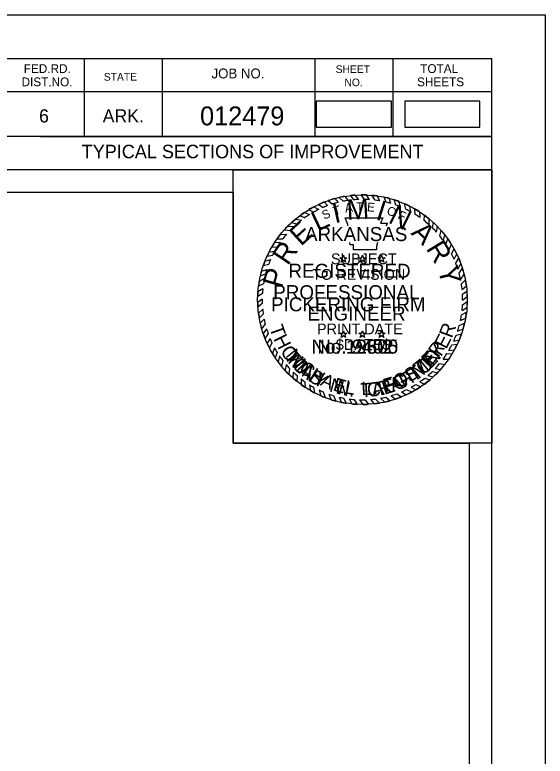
# Model space of a CAD drawing. Extents: x 1373889 to 1374222, y 382002 to 382215.
# Drawn here: x 1374174.7 to 1374221.8, y 382149.1 to 382215 of the extents above; entities that cross this region are included whole.
import ezdxf

# ---------------------------------------------------------------- set-up
doc = ezdxf.new("R2010")
doc.units = 0
for name, color, linetype in [('Default', 7, 'Continuous'), ('R_Border', 7, 'Continuous'), ('R_Border Notes', 7, 'Continuous'), ('R_No Plot', 7, 'Continuous'), ('STAMP_PE_CRAFTON', 7, 'Continuous'), ('STAMP_PE_FOSTER', 7, 'Continuous'), ('STAMP_PE_SEAL-INFO', 7, 'Continuous'), ('STAMP_PE_TAEGTMEYER', 7, 'Continuous'), ('STAMP_PE_TXT', 7, 'Continuous'), ('STAMP_PRELIMINARY', 7, 'Continuous')]:
    doc.layers.add(name, color=color, linetype=linetype)

msp = doc.modelspace()

# ---------------------------------------------------------------- linework, layer by layer
at = {"layer": 'Default'}
for points in [[(1374201.483, 382205.02), (1374208.166, 382205.02), (1374208.166, 382207.33), (1374201.483, 382207.33)], [(1374209.353, 382205.02), (1374216.036, 382205.02), (1374216.036, 382207.33), (1374209.353, 382207.33)]]:
    msp.add_lwpolyline(points, close=True, dxfattribs=at)
at = {"layer": 'R_Border'}
for p, q in [((1373900.915, 382211.115), (1374217.095, 382211.115)), ((1374180.835, 382211.115), (1374180.835, 382204.175)), ((1374187.775, 382211.115), (1374187.775, 382204.175)), ((1374201.355, 382211.115), (1374201.355, 382204.175)), ((1374208.295, 382211.115), (1374208.295, 382204.175)), ((1374217.095, 382005.655), (1374217.095, 382211.115)), ((1374217.095, 382208.175), (1374173.995, 382208.175)), ((1374217.095, 382208.195), (1374217.095, 382208.195)), ((1374217.095, 382204.175), (1374173.995, 382204.175)), ((1374176.955, 382204.175), (1374217.095, 382204.175)), ((1374217.095, 382201.235), (1374154.455, 382201.235))]:
    msp.add_line(p, q, dxfattribs=at)
at = {"layer": 'R_No Plot'}
for points in [[(1373888.507, 382215.01), (1374221.847, 382215.01), (1374221.847, 382001.672), (1373888.507, 382001.672)], [(1374215.095, 382110.385), (1373902.915, 382110.385), (1373902.915, 382209.115), (1374152.455, 382209.115), (1374152.455, 382199.235), (1374169.995, 382199.235), (1374194.095, 382199.235), (1374194.095, 382176.903), (1374215.095, 382176.903)], [(1373902.915, 382209.115), (1374152.455, 382209.115), (1374152.455, 382199.235), (1374169.995, 382199.235), (1374194.095, 382199.235), (1374194.095, 382176.903), (1374215.095, 382176.903), (1374215.095, 382007.655), (1373902.915, 382007.655)], [(1374194.095, 382201.235), (1374217.095, 382201.235), (1374217.095, 382176.903), (1374194.095, 382176.903)]]:
    msp.add_lwpolyline(points, close=True, dxfattribs=at)
at = {"layer": 'STAMP_PE_SEAL-INFO'}
for p, q in [((1374203.533, 382198.769), (1374203.889, 382198.426)), ((1374204.016, 382198.866), (1374204.315, 382198.499)), ((1374204.531, 382198.939), (1374204.812, 382198.557)), ((1374205.267, 382198.585), (1374204.955, 382198.978)), ((1374205.765, 382198.59), (1374205.486, 382199)), ((1374206.223, 382198.569), (1374205.964, 382198.993)), ((1374206.728, 382198.519), (1374206.436, 382198.962)), ((1374207.154, 382198.454), (1374206.897, 382198.909)), ((1374207.716, 382198.335), (1374207.542, 382198.795)), ((1374208.118, 382198.227), (1374207.959, 382198.696)), ((1374201.699, 382198.147), (1374202.088, 382197.872)), ((1374202.207, 382198.363), (1374202.501, 382198.037)), ((1374202.554, 382198.491), (1374202.935, 382198.185)), ((1374203.145, 382198.673), (1374203.433, 382198.325)), ((1374208.57, 382198.08), (1374208.428, 382198.559)), ((1374208.988, 382197.92), (1374208.844, 382198.416)), ((1374209.449, 382197.715), (1374209.347, 382198.212)), ((1374200.433, 382197.441), (1374200.875, 382197.239)), ((1374200.82, 382197.685), (1374201.252, 382197.462)), ((1374201.268, 382197.935), (1374201.731, 382197.71)), ((1374209.895, 382197.485), (1374209.808, 382197.994)), ((1374210.283, 382197.259), (1374210.243, 382197.759)), ((1374210.717, 382196.972), (1374210.686, 382197.487)), ((1374199.636, 382196.847), (1374200.165, 382196.746)), ((1374200.013, 382197.174), (1374200.468, 382196.969)), ((1374204.068, 382196.969), (1374207.412, 382196.969)), ((1374204.189, 382196.662), (1374204.068, 382196.969)), ((1374207.412, 382196.969), (1374207.187, 382196.477)), ((1374211.078, 382196.705), (1374211.112, 382197.193)), ((1374211.524, 382196.333), (1374211.544, 382196.856)), ((1374198.957, 382196.223), (1374199.501, 382196.182)), ((1374199.292, 382196.547), (1374199.751, 382196.408)), ((1374204.293, 382196.364), (1374204.189, 382196.662)), ((1374204.3, 382196.249), (1374204.293, 382196.364)), ((1374207.187, 382196.477), (1374207.82, 382196.477)), ((1374207.82, 382196.477), (1374207.675, 382196.249)), ((1374211.837, 382196.041), (1374211.906, 382196.539)), ((1374212.196, 382195.667), (1374212.263, 382196.193)), ((1374198.288, 382195.468), (1374198.837, 382195.49)), ((1374198.634, 382195.879), (1374199.155, 382195.841)), ((1374212.47, 382195.351), (1374212.606, 382195.822)), ((1374212.794, 382194.934), (1374212.929, 382195.433)), ((1374197.776, 382194.754), (1374198.292, 382194.788)), ((1374198.01, 382195.098), (1374198.515, 382195.093)), ((1374204.492, 382194.541), (1374204.465, 382194.758)), ((1374206.929, 382194.758), (1374206.851, 382194.448)), ((1374213.014, 382194.619), (1374213.191, 382195.082)), ((1374197.529, 382194.353), (1374198.019, 382194.373)), ((1374204.806, 382194.541), (1374204.492, 382194.541)), ((1374204.806, 382194.11), (1374204.806, 382194.541)), ((1374206.836, 382194.11), (1374204.806, 382194.11)), ((1374206.851, 382194.448), (1374206.836, 382194.11)), ((1374213.322, 382194.121), (1374213.504, 382194.613)), ((1374213.521, 382193.755), (1374213.748, 382194.199)), ((1374197.11, 382193.541), (1374197.613, 382193.645)), ((1374197.298, 382193.93), (1374197.797, 382193.995)), ((1374213.752, 382193.271), (1374213.978, 382193.756)), ((1374196.776, 382192.702), (1374197.261, 382192.838)), ((1374196.926, 382193.108), (1374197.431, 382193.255)), ((1374213.893, 382192.934), (1374214.156, 382193.367)), ((1374214.087, 382192.385), (1374214.358, 382192.859)), ((1374196.62, 382192.199), (1374197.097, 382192.368)), ((1374214.195, 382192.02), (1374214.489, 382192.472)), ((1374196.879, 382191.545), (1374196.414, 382191.296)), ((1374196.515, 382191.792), (1374196.985, 382191.984)), ((1374214.328, 382191.461), (1374214.647, 382191.908)), ((1374196.794, 382191.087), (1374196.348, 382190.864)), ((1374214.397, 382191.081), (1374214.751, 382191.434)), ((1374214.463, 382190.572), (1374214.836, 382190.908)), ((1374196.698, 382190.226), (1374196.277, 382189.969)), ((1374196.735, 382190.651), (1374196.298, 382190.37)), ((1374214.496, 382190.154), (1374214.886, 382190.446)), ((1374196.682, 382189.733), (1374196.276, 382189.397)), ((1374214.497, 382189.231), (1374214.916, 382189.508)), ((1374214.508, 382189.636), (1374214.913, 382189.958)), ((1374196.688, 382189.326), (1374196.297, 382189.001)), ((1374196.722, 382188.83), (1374196.35, 382188.474)), ((1374214.457, 382188.725), (1374214.892, 382188.981)), ((1374196.773, 382188.401), (1374196.419, 382188.028)), ((1374214.407, 382188.336), (1374214.85, 382188.556)), ((1374196.852, 382187.942), (1374196.513, 382187.575)), ((1374196.946, 382187.523), (1374196.633, 382187.108)), ((1374214.208, 382187.385), (1374214.68, 382187.586)), ((1374214.316, 382187.836), (1374214.771, 382188.032)), ((1374197.069, 382187.076), (1374196.775, 382186.658)), ((1374214.061, 382186.89), (1374214.552, 382187.091)), ((1374197.21, 382186.653), (1374196.929, 382186.241)), ((1374197.376, 382186.227), (1374197.115, 382185.804)), ((1374213.927, 382186.51), (1374214.409, 382186.641)), ((1374197.548, 382185.843), (1374197.321, 382185.383)), ((1374213.552, 382185.66), (1374214.04, 382185.728)), ((1374213.713, 382185.996), (1374214.201, 382186.092)), ((1374197.783, 382185.385), (1374197.592, 382184.895)), ((1374198.019, 382184.981), (1374197.835, 382184.511)), ((1374213.108, 382184.881), (1374213.585, 382184.874)), ((1374213.279, 382185.161), (1374213.78, 382185.215)), ((1374198.221, 382184.67), (1374198.112, 382184.118)), ((1374198.502, 382184.279), (1374198.4, 382183.749)), ((1374212.768, 382184.386), (1374213.273, 382184.389)), ((1374198.806, 382183.902), (1374198.719, 382183.382)), ((1374199.109, 382183.564), (1374199.047, 382183.042)), ((1374212.077, 382183.559), (1374212.554, 382183.474)), ((1374212.46, 382183.992), (1374212.922, 382183.913)), ((1374199.431, 382183.239), (1374199.401, 382182.71)), ((1374199.775, 382182.926), (1374199.772, 382182.397)), ((1374211.416, 382182.928), (1374211.887, 382182.799)), ((1374211.822, 382183.3), (1374212.263, 382183.162)), ((1374200.135, 382182.632), (1374200.154, 382182.107)), ((1374200.474, 382182.382), (1374200.51, 382181.864)), ((1374210.685, 382182.36), (1374211.124, 382182.171)), ((1374211.145, 382182.703), (1374211.613, 382182.558)), ((1374200.901, 382182.1), (1374200.962, 382181.588)), ((1374201.251, 382181.894), (1374201.342, 382181.381)), ((1374201.732, 382181.644), (1374201.889, 382181.123)), ((1374209.519, 382181.674), (1374210.003, 382181.463)), ((1374209.927, 382181.887), (1374210.344, 382181.655)), ((1374210.341, 382182.133), (1374210.791, 382181.937)), ((1374202.105, 382181.476), (1374202.278, 382180.965)), ((1374202.597, 382181.283), (1374202.807, 382180.782)), ((1374203.007, 382181.148), (1374203.233, 382180.659)), ((1374203.515, 382181.01), (1374203.727, 382180.544)), ((1374203.912, 382180.924), (1374204.159, 382180.466)), ((1374207.196, 382180.909), (1374207.584, 382180.57)), ((1374207.688, 382181.013), (1374208.066, 382180.688)), ((1374208.148, 382181.137), (1374208.564, 382180.84)), ((1374208.64, 382181.301), (1374209.083, 382181.032)), ((1374209.06, 382181.465), (1374209.483, 382181.204)), ((1374204.413, 382180.843), (1374204.652, 382180.403)), ((1374204.849, 382180.795), (1374205.123, 382180.367)), ((1374205.334, 382180.768), (1374205.636, 382180.355)), ((1374205.794, 382180.766), (1374206.137, 382180.371)), ((1374206.312, 382180.793), (1374206.638, 382180.413)), ((1374206.75, 382180.839), (1374207.123, 382180.481))]:
    msp.add_line(p, q, dxfattribs=at)
for radius, start, end in [(9.323, 99.75254, 102.77648), (9.323, 93.93815, 96.55172), (9.323, 87.72979, 90.67067), (9.323, 81.97315, 84.82355), (9.323, 75.31251, 77.94263), (9.323, 111.31242, 114.70259), (8.914, 110.30864, 113.16588), (9.323, 105.23389, 109.03519), (8.914, 104.03521, 107.36155), (8.914, 98.25799, 101.03289), (8.914, 92.11016, 95.03666), (8.914, 85.96279, 88.9097), (8.914, 79.92642, 82.69597), (8.914, 73.55748, 76.23144), (9.323, 69.60611, 72.30577), (8.914, 67.62483, 70.50398), (9.323, 63.13288, 66.2704), (9.323, 123.61993, 126.59063), (9.323, 117.65441, 120.80988), (8.914, 115.68692, 119.15827), (8.914, 61.15575, 64.37837), (9.323, 56.90029, 60.09423), (9.323, 129.73259, 132.53764), (8.914, 127.52969, 130.96829), (8.914, 121.97456, 125.11001), (8.914, 54.92383, 58.27016), (9.323, 50.3492, 53.71593), (9.323, 135.40208, 138.30314), (8.914, 133.13306, 136.25623), (8.914, 48.30163, 52.03953), (9.323, 44.3405, 47.39292), (9.323, 141.60556, 144.44865), (8.914, 139.30101, 142.58729), (8.914, 42.22116, 45.55119), (9.323, 38.12472, 41.23157), (9.323, 147.00719, 149.89904), (8.914, 145.01972, 148.21036), (8.914, 36.13503, 39.53106), (9.323, 31.96138, 35.42937), (8.914, 29.90321, 33.66454), (9.323, 25.93909, 29.01247), (9.323, 152.86398, 155.51889), (8.914, 151.03153, 153.57304), (8.914, 23.77322, 27.22114), (9.323, 158.40766, 161.07015), (8.914, 156.34018, 159.23194), (8.914, 17.68022, 21.42509), (9.323, 19.95381, 23.31409), (9.323, 164.3068, 166.89395), (8.914, 162.43309, 165.00133), (9.323, 13.84205, 17.44468), (8.914, 167.90481, 170.90393), (8.914, 11.54445, 15.23639), (9.323, 170.0003, 172.68778), (8.914, 5.7599, 9.06056), (9.323, 7.58519, 10.86211), (9.323, 175.74093, 178.2066), (8.914, 173.73, 176.47337), (8.914, 359.73289, 3.06392), (9.323, 1.72155, 4.72681), (8.914, 179.64537, 182.26333), (9.323, 355.71562, 358.95694), (9.323, 181.72508, 184.16255), (8.914, 185.45389, 188.23401), (8.914, 353.86319, 357.12742), (9.323, 187.42037, 190.19271), (8.914, 348.07782, 351.34355), (9.323, 349.83047, 353.08845), (9.323, 193.03695, 195.99732), (8.914, 191.22736, 193.98583), (9.323, 343.89247, 347.03502), (8.914, 196.96751, 199.83526), (8.914, 341.77699, 345.09248), (9.323, 198.89671, 201.62812), (8.914, 202.77613, 205.47915), (8.914, 335.6038, 339.18578), (9.323, 337.38367, 340.99332), (9.323, 204.54793, 207.43282), (8.914, 329.55488, 333.20757), (9.323, 331.40371, 334.93315), (9.323, 210.86355, 213.65709), (8.914, 208.78826, 211.79343), (8.914, 323.58513, 327.44069), (9.323, 325.44052, 328.98725), (8.914, 214.18375, 217.27474), (9.323, 216.61154, 219.49098), (8.914, 220.39088, 223.30564), (8.914, 316.65308, 320.37109), (9.323, 318.28455, 321.80429), (9.323, 222.47995, 225.38008), (8.914, 226.24938, 229.24068), (8.914, 310.77436, 314.31605), (9.323, 312.45177, 315.66328), (9.323, 228.36648, 231.34802), (8.914, 232.22904, 234.93361), (8.914, 304.82299, 308.51428), (9.323, 306.37206, 310.20799), (9.323, 234.29502, 236.94517), (8.914, 238.22227, 240.83529), (9.323, 240.1977, 242.86128), (8.914, 244.32043, 246.94859), (8.914, 292.87452, 296.11851), (8.914, 299.07679, 302.17235), (9.323, 300.62101, 303.87026), (9.323, 246.57598, 249.15579), (8.914, 250.34912, 253.12157), (8.914, 256.50505, 259.11916), (8.914, 280.34588, 283.58137), (8.914, 286.64233, 289.97826), (9.323, 288.57086, 291.97334), (9.323, 294.64808, 298.21662), (9.323, 252.59667, 255.32518), (9.323, 258.44328, 261.13983), (8.914, 262.37828, 265.20115), (9.323, 264.19784, 267.10092), (8.914, 268.3215, 271.27698), (9.323, 270.25484, 273.33609), (8.914, 274.61565, 277.44863), (9.323, 276.42389, 279.43574), (9.323, 282.31994, 285.37019)]:
    msp.add_arc((1374205.595, 382189.678), radius, start, end, dxfattribs=at)
at = {"layer": 'STAMP_PE_TXT'}
for p, q in [((1374203.821, 382193.393), (1374203.897, 382193.626)), ((1374203.897, 382193.626), (1374203.973, 382193.393)), ((1374205.519, 382193.393), (1374205.595, 382193.626)), ((1374205.595, 382193.626), (1374205.671, 382193.393)), ((1374207.217, 382193.393), (1374207.293, 382193.626)), ((1374207.293, 382193.626), (1374207.369, 382193.393)), ((1374203.774, 382193.249), (1374203.576, 382193.393)), ((1374203.576, 382193.393), (1374203.821, 382193.393)), ((1374203.699, 382193.016), (1374203.774, 382193.249)), ((1374203.897, 382193.16), (1374203.699, 382193.016)), ((1374204.095, 382193.016), (1374203.897, 382193.16)), ((1374203.973, 382193.393), (1374204.218, 382193.393)), ((1374204.218, 382193.393), (1374204.02, 382193.249)), ((1374204.02, 382193.249), (1374204.095, 382193.016)), ((1374205.472, 382193.249), (1374205.274, 382193.393)), ((1374205.274, 382193.393), (1374205.519, 382193.393)), ((1374205.397, 382193.016), (1374205.472, 382193.249)), ((1374205.595, 382193.16), (1374205.397, 382193.016)), ((1374205.793, 382193.016), (1374205.595, 382193.16)), ((1374205.671, 382193.393), (1374205.916, 382193.393)), ((1374205.916, 382193.393), (1374205.718, 382193.249)), ((1374205.718, 382193.249), (1374205.793, 382193.016)), ((1374207.17, 382193.249), (1374206.972, 382193.393)), ((1374206.972, 382193.393), (1374207.217, 382193.393)), ((1374207.095, 382193.016), (1374207.17, 382193.249)), ((1374207.293, 382193.16), (1374207.095, 382193.016)), ((1374207.491, 382193.016), (1374207.293, 382193.16)), ((1374207.369, 382193.393), (1374207.614, 382193.393)), ((1374207.614, 382193.393), (1374207.416, 382193.249)), ((1374207.416, 382193.249), (1374207.491, 382193.016)), ((1374203.821, 382186.686), (1374203.897, 382186.919)), ((1374203.897, 382186.919), (1374203.973, 382186.686)), ((1374205.519, 382186.686), (1374205.595, 382186.919)), ((1374205.595, 382186.919), (1374205.671, 382186.686)), ((1374207.217, 382186.686), (1374207.293, 382186.919)), ((1374207.293, 382186.919), (1374207.369, 382186.686)), ((1374203.774, 382186.542), (1374203.576, 382186.686)), ((1374203.576, 382186.686), (1374203.821, 382186.686)), ((1374203.699, 382186.309), (1374203.774, 382186.542)), ((1374203.897, 382186.453), (1374203.699, 382186.309)), ((1374204.095, 382186.309), (1374203.897, 382186.453)), ((1374203.973, 382186.686), (1374204.218, 382186.686)), ((1374204.218, 382186.686), (1374204.02, 382186.542)), ((1374204.02, 382186.542), (1374204.095, 382186.309)), ((1374205.472, 382186.542), (1374205.274, 382186.686)), ((1374205.274, 382186.686), (1374205.519, 382186.686)), ((1374205.397, 382186.309), (1374205.472, 382186.542)), ((1374205.595, 382186.453), (1374205.397, 382186.309)), ((1374205.793, 382186.309), (1374205.595, 382186.453)), ((1374205.671, 382186.686), (1374205.916, 382186.686)), ((1374205.916, 382186.686), (1374205.718, 382186.542)), ((1374205.718, 382186.542), (1374205.793, 382186.309)), ((1374207.17, 382186.542), (1374206.972, 382186.686)), ((1374206.972, 382186.686), (1374207.217, 382186.686)), ((1374207.095, 382186.309), (1374207.17, 382186.542)), ((1374207.293, 382186.453), (1374207.095, 382186.309)), ((1374207.491, 382186.309), (1374207.293, 382186.453)), ((1374207.369, 382186.686), (1374207.614, 382186.686)), ((1374207.614, 382186.686), (1374207.416, 382186.542)), ((1374207.416, 382186.542), (1374207.491, 382186.309))]:
    msp.add_line(p, q, dxfattribs=at)
at = {"layer": 'STAMP_PRELIMINARY'}
msp.add_circle((1374205.595, 382189.678), 9.323, dxfattribs=at)

# ---------------------------------------------------------------- texts
at = {"layer": 'R_Border'}
for s, height, p in [('FED.RD.', 0.7819, (1374175.475, 382209.835)), ('TOTAL', 0.7819, (1374210.735, 382209.835)), ('JOB NO.', 0.8792, (1374192.175, 382209.355)), ('SHEET', 0.684, (1374203.215, 382209.835)), ('DIST.NO.', 0.7819, (1374175.275, 382208.655)), ('STATE', 0.684, (1374182.595, 382209.155)), ('NO.', 0.684, (1374203.995, 382208.655)), ('SHEETS', 0.7819, (1374210.455, 382208.655)), ('6', 1.172, (1374176.835, 382205.435)), ('ARK.', 1.1723, (1374182.495, 382205.435))]:
    msp.add_text(s, height=height, dxfattribs=at).set_placement(p)
at = {"layer": 'R_Border Notes'}
for s, height, p in [('012479', 1.68, (1374191.153, 382205.18)), ('TYPICAL SECTIONS OF IMPROVEMENT', 1.2, (1374180.627, 382202.254))]:
    msp.add_text(s, height=height, dxfattribs=at).set_placement(p)
at = {"layer": 'STAMP_PE_CRAFTON'}
msp.add_text('No. 12370', height=1.25, dxfattribs=at).set_placement((1374201.057, 382184.875))
for s, rotation, p in [('T', 310.74416, (1374198.561, 382184.575)), ('N', 49.24107, (1374211.877, 382183.7)), ('O', 317.64216, (1374199.228, 382183.764)), ('O', 41.83906, (1374211.03, 382182.918)), ('N', 324.45371, (1374200.074, 382182.979)), ('T', 34.11362, (1374210.172, 382182.317)), ('Y', 331.16864, (1374201.107, 382182.263)), ('F', 28.78207, (1374209.256, 382181.807)), ('N', 347.47515, (1374203.162, 382181.347)), ('C', 6.01169, (1374206.066, 382181.019)), ('R', 14.81888, (1374207.163, 382181.134)), ('A', 20.51248, (1374208.276, 382181.433)), ('.', 356.89262, (1374204.391, 382181.07))]:
    msp.add_text(s, height=1.25, rotation=rotation, dxfattribs=at).set_placement(p)
at = {"layer": 'STAMP_PE_FOSTER'}
msp.add_text('No. 9402', height=1.25, dxfattribs=at).set_placement((1374201.581, 382184.875))
for s, rotation, p in [('R', 54.5031, (1374212.319, 382184.489)), ('M', 308.33902, (1374198.711, 382184.7)), ('E', 46.96131, (1374211.596, 382183.668)), ('I', 314.18423, (1374199.509, 382183.762)), ('T', 39.41938, (1374210.737, 382182.918)), ('C', 319.87327, (1374199.863, 382183.409)), ('H', 327.72349, (1374200.792, 382182.673)), ('S', 31.72336, (1374209.786, 382182.29)), ('A', 335.72761, (1374201.773, 382182.091)), ('O', 23.71897, (1374208.674, 382181.76)), ('E', 343.5779, (1374202.91, 382181.62)), ('L', 350.81148, (1374203.969, 382181.343)), ('L', 1.26658, (1374205.508, 382181.186)), ('F', 15.86908, (1374207.63, 382181.432)), ('.', 6.80354, (1374206.555, 382181.245))]:
    msp.add_text(s, height=1.2, rotation=rotation, dxfattribs=at).set_placement(p)
at = {"layer": 'STAMP_PE_TAEGTMEYER'}
for s, rotation, p in [('T', 289.64597, (1374197.289, 382187.188)), ('R', 69.57001, (1374213.54, 382186.192)), ('H', 296.73386, (1374197.649, 382186.203)), ('E', 63.0984, (1374213.041, 382185.211)), ('O', 303.77078, (1374198.242, 382185.095)), ('Y', 53.99864, (1374212.372, 382184.27)), ('M', 314.20329, (1374198.897, 382184.144)), ('E', 46.80938, (1374211.633, 382183.455)), ('M', 39.30005, (1374210.593, 382182.576)), ('A', 321.0594, (1374199.859, 382183.18)), ('T', 31.46601, (1374209.695, 382182.032)), ('S', 327.82385, (1374200.685, 382182.536)), ('G', 23.30524, (1374208.595, 382181.54)), ('N', 344.27273, (1374202.582, 382181.529)), ('T', 3.00609, (1374205.459, 382180.998)), ('A', 8.98261, (1374206.506, 382181.054)), ('E', 17.68363, (1374207.545, 382181.209)), ('.', 350.64643, (1374203.794, 382181.197))]:
    msp.add_text(s, height=1.25, rotation=rotation, dxfattribs=at).set_placement(p)
msp.add_text('No. 19605', height=1.25, dxfattribs=at).set_placement((1374201.057, 382184.875))
at = {"layer": 'STAMP_PE_TXT'}
for s, rotation, p in [('T', 16.311, (1374203.117, 382197.154)), ('A', 9.0679, (1374204.079, 382197.406)), ('T', 1.82479, (1374205.065, 382197.536)), ('E', 355.20019, (1374205.976, 382197.545)), ('S', 23.5541, (1374202.194, 382196.781)), ('O', 342.25065, (1374207.702, 382197.268)), ('F', 335.00755, (1374208.668, 382196.93))]:
    msp.add_text(s, height=0.781, rotation=rotation, dxfattribs=at).set_placement(p)
for s, p in [('ARKANSAS', (1374200.487, 382194.888)), ('REGISTERED', (1374199.012, 382191.619)), ('PROFESSIONAL', (1374197.663, 382189.717)), ('ENGINEER', (1374200.704, 382187.816))]:
    msp.add_text(s, height=1.25, dxfattribs=at).set_placement(p)
at = {"layer": 'STAMP_PRELIMINARY'}
for s, rotation, p in [('I', 12.52485, (1374203.133, 382196.464)), ('M', 3.10738, (1374204.231, 382196.773)), ('I', 342.31637, (1374206.698, 382196.841)), ('N', 333.9382, (1374207.806, 382196.567)), ('L', 25.51305, (1374201.604, 382195.705)), ('E', 42.35784, (1374200.121, 382194.374)), ('A', 315.65789, (1374209.84, 382195.541)), ('R', 56.22922, (1374198.966, 382192.641)), ('R', 301.38306, (1374211.208, 382194.227)), ('Y', 283.25926, (1374212.297, 382192.441)), ('P', 73.91301, (1374198.416, 382190.618))]:
    msp.add_text(s, height=1.8, rotation=rotation, dxfattribs=at).set_placement(p)
for s, height, p in [('SUBJECT', 0.96, (1374202.795, 382192.827)), ('TO REVISION', 0.96, (1374201.13, 382191.442)), ('PICKERING FIRM', 1.25, (1374197.468, 382188.641)), ('PRINT DATE', 0.96, (1374201.552, 382186.593)), ('$DATE$', 0.96, (1374203.229, 382185.208))]:
    msp.add_text(s, height=height, dxfattribs=at).set_placement(p)

doc.saveas('drawing.dxf')
